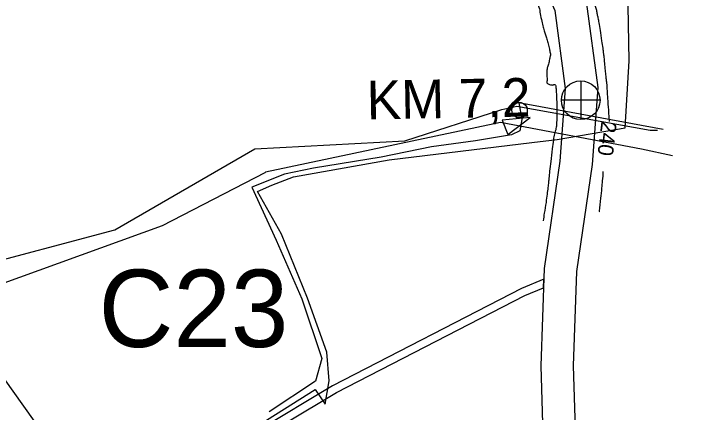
# Model space of a CAD drawing. Extents: x -478232 to -472707, y -1118753 to -1113967.
# Drawn here: x -476775.2 to -476596.9, y -1115588.3 to -1115485.3 of the extents above; entities that cross this region are included whole.
import ezdxf

# ---------------------------------------------------------------- set-up
doc = ezdxf.new("R2010")
doc.units = 0
for name, color, linetype in [('cesty', 7, 'Continuous'), ('el vedeni _VN', 7, 'Continuous'), ('ObPÚ', 7, 'Continuous'), ('staničení toku', 7, 'Continuous'), ('VAK_kanalizace', 7, 'Continuous'), ('vodní plochy', 7, 'Continuous'), ('Vrstevnice_hlavni', 7, 'Continuous'), ('Vrstevnice_popis', 7, 'Continuous')]:
    doc.layers.add(name, color=color, linetype=linetype)

msp = doc.modelspace()

# ---------------------------------------------------------------- linework, layer by layer
at = {"layer": 'cesty'}
msp.add_line((-476648.872, -1115512.777), (-476647.393, -1115516.493), dxfattribs=at)
msp.add_lwpolyline([(-476647.393, -1115516.493), (-476641.679, -1115512.067), (-476648.872, -1115512.777)], dxfattribs=at)
msp.add_circle((-476644.397, -1115510.226), 2, dxfattribs=at)
at = {"layer": 'el vedeni _VN'}
for points in [[(-476960.505, -1115493.233), (-476958.229, -1115494.183), (-476899.623, -1115513.536), (-476849.434, -1115530.972), (-476828.522, -1115538.992), (-476787.371, -1115551.336), (-476749.039, -1115541.109), (-476712.836, -1115520.229), (-476674.078, -1115518.099), (-476648.949, -1115510.002), (-476645.065, -1115509.167), (-476610.607, -1115515.405), (-476608.699, -1115515.336)], [(-476607.29, -1115515.24), (-476644.57, -1115508.27), (-476643.83, -1115512.629), (-476644.33, -1115515.549), (-476646.46, -1115516.549), (-476655.81, -1115518.099), (-476667.18, -1115519.709), (-476680.17, -1115522.329), (-476697.65, -1115525.229), (-476705.17, -1115526.729), (-476713.65, -1115530.139), (-476707.36, -1115543.809), (-476700.72, -1115559.009), (-476695.5, -1115574.439), (-476697.2, -1115580.259), (-476709.142, -1115588.178)]]:
    msp.add_lwpolyline(points, dxfattribs=at)
at = {"layer": 'ObPÚ'}
msp.add_lwpolyline([(-476729.68, -1115602.85), (-476697.22, -1115582.39), (-476694.71, -1115586.24), (-476693.62, -1115580.2), (-476694.23, -1115572.79), (-476699.22, -1115558.83), (-476705.96, -1115542.27), (-476712.2, -1115531.25), (-476708.5, -1115529.58), (-476702.86, -1115527.42), (-476678.15, -1115523.05), (-476641.21, -1115518.56), (-476634.68, -1115517.79), (-476617.05, -1115514.79), (-476616.07, -1115497.42), (-476616.77, -1115459.57)], dxfattribs=at)
at = {"layer": 'staničení toku'}
for p, q in [((-476628.592, -1115502.652), (-476628.592, -1115512.652)), ((-476623.592, -1115507.652), (-476633.592, -1115507.652))]:
    msp.add_line(p, q, dxfattribs=at)
msp.add_circle((-476628.592, -1115507.652), 5, dxfattribs=at)
at = {"layer": 'VAK_kanalizace'}
for points in [[(-476649.342, -1115513.392), (-476710.071, -1115526.273), (-476710.315, -1115526.399)], [(-476612.869, -1115520.261), (-476649.342, -1115513.392)], [(-476604.866, -1115522.007), (-476612.869, -1115520.261)], [(-476710.315, -1115526.399), (-476736.837, -1115540.074)], [(-476596.91, -1115841.27), (-476639.491, -1115781.004), (-476677.085, -1115721.078), (-476807.031, -1115538.469)], [(-476736.837, -1115540.074), (-476784.756, -1115557.442)]]:
    msp.add_lwpolyline(points, dxfattribs=at)
at = {"layer": 'vodní plochy'}
for points in [[(-476629.941, -1115592.562), (-476630.454, -1115576.275), (-476629.578, -1115551.927), (-476625.532, -1115524.267), (-476624.09, -1115504.314), (-476627.078, -1115482.147), (-476632.667, -1115469.328), (-476643.336, -1115456.47), (-476657.484, -1115438.865), (-476674.172, -1115427.063), (-476706.139, -1115412.85), (-476729.984, -1115399.76), (-476740.488, -1115387.341), (-476748.689, -1115366.395), (-476759.924, -1115343.455), (-476770.83, -1115321.401), (-476783.513, -1115303.098)], [(-476778.137, -1115325.707), (-476767.514, -1115347.19), (-476756.439, -1115369.803), (-476747.853, -1115391.732), (-476735.43, -1115406.42), (-476709.899, -1115420.436), (-476678.373, -1115434.452), (-476663.336, -1115445.087), (-476649.888, -1115461.82), (-476639.942, -1115473.808), (-476635.303, -1115484.446), (-476632.59, -1115504.577), (-476633.946, -1115523.349), (-476638.014, -1115551.16), (-476638.918, -1115576.256), (-476638.355, -1115594.111)], [(-476638.113, -1115553.904), (-476643.882, -1115556.28), (-476692.746, -1115581.454), (-476731.259, -1115604.531), (-476764.657, -1115629.099), (-476802.386, -1115652.775), (-476819.266, -1115663.622), (-476873.466, -1115698.453), (-476876.962, -1115700.938), (-476893.934, -1115713.636)], [(-476638.192, -1115556.1), (-476638.113, -1115553.904)], [(-476818.184, -1115665.304), (-476801.314, -1115654.463), (-476763.531, -1115630.753), (-476730.149, -1115606.199), (-476691.774, -1115583.202), (-476643.042, -1115558.096), (-476638.192, -1115556.1)]]:
    msp.add_lwpolyline(points, dxfattribs=at)
at = {"layer": 'Vrstevnice_hlavni'}
for points in [[(-476675.172, -1115442.891), (-476674.626, -1115443.23), (-476674.326, -1115443.444), (-476673.998, -1115443.703), (-476673.643, -1115444.006), (-476672.012, -1115445.487), (-476669.106, -1115448.147), (-476664.923, -1115451.985), (-476662.048, -1115454.626), (-476660.479, -1115456.072), (-476660.217, -1115456.321), (-476659.967, -1115456.568), (-476659.729, -1115456.815), (-476659.502, -1115457.059), (-476658.339, -1115458.137), (-476656.24, -1115460.049), (-476653.205, -1115462.795), (-476651.104, -1115464.702), (-476649.939, -1115465.77), (-476649.71, -1115466), (-476649.538, -1115466.17), (-476649.425, -1115466.28), (-476649.37, -1115466.33), (-476649.316, -1115466.382), (-476649.261, -1115466.437), (-476649.207, -1115466.495), (-476648.681, -1115467.234), (-476647.683, -1115468.656), (-476646.214, -1115470.761), (-476645.234, -1115472.165), (-476644.744, -1115472.867), (-476644.743, -1115472.868), (-476644.742, -1115472.869), (-476644.741, -1115472.87), (-476644.189, -1115473.878), (-476643.085, -1115475.892), (-476641.429, -1115478.913), (-476640.313, -1115480.954), (-476639.736, -1115482.014), (-476639.7, -1115482.095), (-476639.658, -1115482.232), (-476639.61, -1115482.426), (-476639.555, -1115482.676), (-476639.518, -1115482.842), (-476639.5, -1115482.925), (-476639.501, -1115482.924), (-476639.378, -1115483.565), (-476639.133, -1115484.846), (-476638.766, -1115486.769), (-476638.404, -1115488.387), (-476638.048, -1115489.699), (-476637.698, -1115490.706), (-476637.354, -1115491.828), (-476637.017, -1115493.063), (-476636.686, -1115494.413), (-476636.484, -1115495.376), (-476636.411, -1115495.954), (-476636.467, -1115496.145), (-476636.546, -1115496.498), (-476636.648, -1115497.014), (-476636.772, -1115497.691), (-476636.911, -1115498.298), (-476637.064, -1115498.836), (-476637.232, -1115499.305), (-476637.332, -1115499.88), (-476637.364, -1115500.562), (-476637.328, -1115501.351), (-476637.305, -1115501.916), (-476637.295, -1115502.255), (-476637.299, -1115502.369), (-476637.302, -1115502.476), (-476637.305, -1115502.575), (-476637.308, -1115502.666), (-476637.314, -1115502.785), (-476637.323, -1115502.931), (-476637.335, -1115503.105), (-476637.185, -1115503.279), (-476636.871, -1115503.453), (-476636.395, -1115503.627), (-476635.985, -1115503.7), (-476635.641, -1115503.673), (-476635.364, -1115503.545), (-476635.163, -1115503.629), (-476635.036, -1115503.926), (-476634.985, -1115504.435), (-476634.924, -1115505.348), (-476634.853, -1115506.665), (-476634.773, -1115508.386), (-476634.73, -1115509.857), (-476634.725, -1115511.078), (-476634.757, -1115512.048), (-476634.794, -1115512.909), (-476634.835, -1115513.661), (-476634.88, -1115514.304), (-476634.986, -1115514.959), (-476635.152, -1115515.626)], [(-476649.162, -1115445.383), (-476649.04, -1115445.49), (-476648.941, -1115445.572), (-476648.865, -1115445.628), (-476648.813, -1115445.658), (-476648.733, -1115445.739), (-476648.624, -1115445.87), (-476648.485, -1115446.051), (-476647.64, -1115446.857), (-476646.086, -1115448.29), (-476643.825, -1115450.347), (-476642.282, -1115451.76), (-476641.459, -1115452.527), (-476641.355, -1115452.649), (-476640.975, -1115453.309), (-476640.32, -1115454.508), (-476639.39, -1115456.245), (-476638.725, -1115457.487), (-476638.325, -1115458.232), (-476638.189, -1115458.482), (-476638.072, -1115458.678), (-476637.972, -1115458.818), (-476637.89, -1115458.904), (-476637.818, -1115458.998), (-476637.755, -1115459.099), (-476637.701, -1115459.209), (-476637.598, -1115459.369), (-476637.444, -1115459.58), (-476637.241, -1115459.842), (-476636.687, -1115460.676), (-476635.784, -1115462.084), (-476634.529, -1115464.064), (-476633.647, -1115465.448), (-476633.135, -1115466.236), (-476632.994, -1115466.428), (-476632.881, -1115466.609), (-476632.795, -1115466.779), (-476632.737, -1115466.94), (-476632.656, -1115467.089), (-476632.553, -1115467.228), (-476632.427, -1115467.356), (-476631.9, -1115468.24), (-476630.973, -1115469.88), (-476629.645, -1115472.275), (-476628.725, -1115473.931), (-476628.212, -1115474.846), (-476628.107, -1115475.022), (-476628.006, -1115475.185), (-476627.909, -1115475.337), (-476627.816, -1115475.477), (-476627.693, -1115475.718), (-476627.539, -1115476.06), (-476627.355, -1115476.503), (-476626.941, -1115477.57), (-476626.298, -1115479.261), (-476625.426, -1115481.577), (-476624.826, -1115483.283), (-476624.499, -1115484.379), (-476624.444, -1115484.865), (-476624.364, -1115485.358), (-476624.256, -1115485.859), (-476624.123, -1115486.367), (-476623.9, -1115487.607), (-476623.587, -1115489.58), (-476623.185, -1115492.284), (-476622.903, -1115494.208), (-476622.739, -1115495.352), (-476622.695, -1115495.716), (-476622.601, -1115496.605), (-476622.457, -1115498.019), (-476622.264, -1115499.957), (-476622.111, -1115501.417), (-476622, -1115502.399), (-476621.93, -1115502.903), (-476621.882, -1115503.325), (-476621.857, -1115503.666), (-476621.854, -1115503.924), (-476621.783, -1115505.089), (-476621.644, -1115507.16), (-476621.437, -1115510.137), (-476621.299, -1115512.128), (-476621.23, -1115513.132), (-476621.229, -1115513.166)], [(-476635.152, -1115515.626), (-476635.379, -1115516.305), (-476635.654, -1115517.842), (-476635.977, -1115520.236), (-476636.347, -1115523.487), (-476636.628, -1115525.999), (-476636.819, -1115527.773), (-476636.921, -1115528.807), (-476637.078, -1115530.196), (-476637.292, -1115531.938), (-476637.562, -1115534.035), (-476638.001, -1115536.851), (-476638.334, -1115538.813)], [(-476623.777, -1115536.473), (-476623.758, -1115536.31), (-476623.38, -1115532.975), (-476623.098, -1115530.352), (-476622.914, -1115528.44), (-476622.74, -1115526.038)]]:
    msp.add_spline(points, degree=3, dxfattribs=at)

# ---------------------------------------------------------------- texts
at = {"layer": 'cesty'}
msp.add_text('C23', height=20, rotation=359.99999, dxfattribs=at).set_placement((-476753.248, -1115571.432))
at = {"layer": 'staničení toku'}
msp.add_text('KM 7,2', height=10, rotation=1.06713, dxfattribs=at).set_placement((-476683.855, -1115512.624))
at = {"layer": 'Vrstevnice_popis'}
msp.add_text(' 240 ', height=4, rotation=263.30365, dxfattribs=at).set_placement((-476623.038, -1115511.42))

doc.saveas('drawing.dxf')
